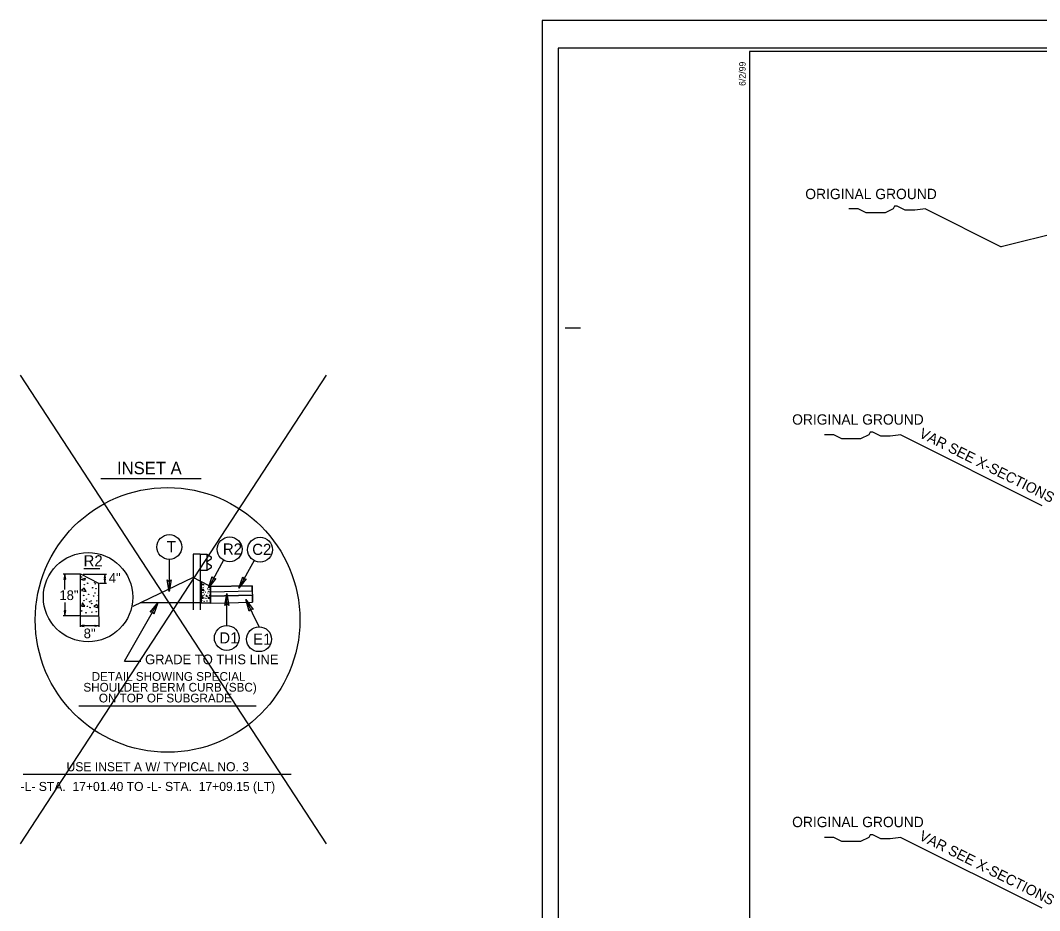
# Model space of a CAD drawing. Extents: x 573732 to 574187, y -53389 to -53257.
# Drawn here: x 573731.8 to 573830.3, y -53342.9 to -53256.9 of the extents above; entities that cross this region are included whole.
import ezdxf

# ---------------------------------------------------------------- set-up
doc = ezdxf.new("R2010")
doc.units = 0
for name, color, linetype in [('Old_Level_1', 7, 'Continuous'), ('Old_Level_11', 7, 'Continuous'), ('Prop Dimension', 7, 'Continuous'), ('Prop Shade Light', 7, 'Continuous'), ('Prop Shade Medium', 7, 'Continuous'), ('Prop Terminator CELL', 7, 'Continuous'), ('Sheet Cutting Line CELL', 7, 'Continuous'), ('Sheet Plot Border Inside CELL', 7, 'Continuous'), ('Sheet Plot Border Outside CELL', 7, 'Continuous'), ('Sheet Typical CELL', 7, 'Continuous'), ('Typical Curb CELL', 7, 'Continuous'), ('Typical Detail Wedge2 CELL', 7, 'Continuous'), ('Typical Guardrail CELL', 7, 'Continuous'), ('Typical ID Circle CELL', 7, 'Continuous'), ('Typical Pavement Slope CELL', 7, 'Continuous'), ('Typical Pavement Slope Information CELL', 7, 'Continuous'), ('Typical Shoulder Slope CELL', 7, 'Continuous'), ('Typical Slope Point Local CELL', 7, 'Continuous'), ('Typical Terminator CELL', 7, 'Continuous'), ('Typical Text General CELL', 7, 'Continuous'), ('Typical Text ID Circle CELL', 7, 'Continuous'), ('Typical Text Label CELL', 7, 'Continuous')]:
    doc.layers.add(name, color=color, linetype=linetype)

msp = doc.modelspace()

# ---------------------------------------------------------------- linework, layer by layer
at = {"layer": 'Old_Level_1'}
for p in [(573819.248, -53275.156), (573837.319, -53276.137)]:
    msp.add_line(p, (573826.579, -53278.822), dxfattribs=at)
at = {"layer": 'Old_Level_11'}
for points in [[(573736.234, -53310.921), (573736.142, -53310.411), (573736.055, -53310.926), (573736.146, -53310.86)], [(573740.076, -53310.794), (573740.007, -53310.411), (573739.942, -53310.797), (573740.009, -53310.747)], [(573739.945, -53310.906), (573740.007, -53311.29), (573740.079, -53310.906), (573740.011, -53310.954)], [(573736.06, -53313.949), (573736.142, -53314.461), (573736.239, -53313.948), (573736.147, -53314.013)], [(573738.008, -53315.337), (573737.625, -53315.403), (573738.01, -53315.471), (573737.961, -53315.403)], [(573739.042, -53315.337), (573739.425, -53315.403), (573739.04, -53315.471), (573739.089, -53315.403)]]:
    msp.add_lwpolyline(points, close=True, dxfattribs=at)
at = {"layer": 'Prop Dimension'}
for p, q in [((573731.844, -53336.476), (573761.397, -53291.214)), ((573761.397, -53336.476), (573731.844, -53291.214)), ((573737.618, -53310.411), (573735.986, -53310.411)), ((573736.142, -53311.894), (573736.142, -53310.411)), ((573737.918, -53310.411), (573740.16, -53310.411)), ((573740.007, -53310.411), (573740.007, -53311.29)), ((573740.16, -53311.311), (573739.488, -53311.311)), ((573736.142, -53313.169), (573736.142, -53314.461)), ((573741.884, -53318.814), (573745.12, -53313.202)), ((573737.562, -53314.461), (573735.986, -53314.461)), ((573737.625, -53314.524), (573737.625, -53315.523)), ((573739.425, -53314.524), (573739.425, -53315.523)), ((573739.425, -53315.403), (573737.625, -53315.403)), ((573741.884, -53318.814), (573743.463, -53318.814))]:
    msp.add_line(p, q, dxfattribs=at)
msp.add_circle((573738.381, -53312.646), 4.313, dxfattribs=at)
at = {"layer": 'Prop Shade Light'}
for p, q in [((573754.239, -53312.045), (573754.228, -53311.544)), ((573750.207, -53311.649), (573750.207, -53312.127)), ((573750.207, -53312.127), (573754.239, -53312.045))]:
    msp.add_line(p, q, dxfattribs=at)
msp.add_lwpolyline([(573754.228, -53311.544), (573750.207, -53311.627), (573750.197, -53311.628)], dxfattribs=at)
msp.add_ellipse((573750.196, -53311.649), major_axis=(0, 0.0209), ratio=0.5, start_param=4.712389, end_param=6.268072, dxfattribs=at)
at = {"layer": 'Prop Shade Medium'}
for p, q in [((573754.247, -53312.461), (573750.207, -53312.544)), ((573750.207, -53312.544), (573750.207, -53313.211)), ((573754.261, -53313.128), (573754.247, -53312.461)), ((573750.207, -53313.211), (573754.261, -53313.128))]:
    msp.add_line(p, q, dxfattribs=at)
at = {"layer": 'Prop Terminator CELL'}
for points in [[(573750.716, -53310.847), (573750, -53311.736), (573750.375, -53310.65), (573750.48, -53310.873)], [(573746.421, -53310.984), (573746.227, -53312.109), (573746.027, -53310.978), (573746.227, -53311.122)], [(573753.656, -53310.88), (573752.94, -53311.77), (573753.315, -53310.684), (573753.42, -53310.906)], [(573744.391, -53314.081), (573745.12, -53313.202), (573744.729, -53314.283), (573744.627, -53314.058)]]:
    msp.add_lwpolyline(points, close=True, dxfattribs=at)
at = {"layer": 'Sheet Cutting Line CELL'}
for p, q in [((573984.302, -53256.948), (573782.222, -53256.948)), ((573782.222, -53256.948), (573782.222, -53388.948))]:
    msp.add_line(p, q, dxfattribs=at)
at = {"layer": 'Sheet Plot Border Inside CELL'}
msp.add_lwpolyline([(573983.762, -53259.642), (573783.782, -53259.642), (573783.782, -53386.254), (573983.762, -53386.254)], close=True, dxfattribs=at)
at = {"layer": 'Sheet Plot Border Outside CELL'}
msp.add_lwpolyline([(573984.302, -53256.948), (573782.222, -53256.948), (573782.222, -53388.948), (573984.302, -53388.948)], close=True, dxfattribs=at)
at = {"layer": 'Sheet Typical CELL'}
msp.add_line((573784.442, -53286.648), (573785.942, -53286.648), dxfattribs=at)
msp.add_lwpolyline([(573982.262, -53259.948), (573802.262, -53259.948), (573802.262, -53385.948), (573982.262, -53385.948)], close=True, dxfattribs=at)
at = {"layer": 'Typical Curb CELL'}
for p, q in [((573737.625, -53310.468), (573737.682, -53310.411)), ((573737.625, -53310.468), (573737.625, -53314.461)), ((573739.425, -53311.311), (573737.682, -53310.411)), ((573737.673, -53310.926), (573738.09, -53310.805)), ((573738.045, -53311.049), (573737.673, -53310.926)), ((573738.09, -53310.805), (573738.045, -53311.049)), ((573739.425, -53314.461), (573739.425, -53311.311)), ((573750.207, -53311.627), (573749.194, -53311.105)), ((573749.307, -53311.206), (573749.335, -53311.177)), ((573749.307, -53311.206), (573749.307, -53313.202)), ((573749.331, -53311.435), (573749.539, -53311.374)), ((573749.517, -53311.496), (573749.331, -53311.435)), ((573749.539, -53311.374), (573749.517, -53311.496)), ((573750.207, -53313.202), (573750.207, -53311.627)), ((573738.014, -53311.786), (573737.735, -53311.989)), ((573737.735, -53311.989), (573738.182, -53312.095)), ((573738.182, -53312.095), (573738.014, -53311.786)), ((573749.501, -53311.865), (573749.362, -53311.966)), ((573749.362, -53311.966), (573749.586, -53312.02)), ((573749.416, -53312.572), (573749.37, -53312.726)), ((573749.532, -53312.734), (573749.416, -53312.572)), ((573749.586, -53312.02), (573749.501, -53311.865)), ((573737.844, -53313.201), (573737.751, -53313.508)), ((573737.751, -53313.508), (573738.074, -53313.525)), ((573738.074, -53313.525), (573737.844, -53313.201)), ((573739.213, -53313.353), (573738.935, -53313.556)), ((573738.935, -53313.556), (573739.382, -53313.663)), ((573739.382, -53313.663), (573739.213, -53313.353)), ((573749.307, -53313.202), (573750.207, -53313.202)), ((573749.37, -53312.726), (573749.532, -53312.734)), ((573750.101, -53312.648), (573749.962, -53312.75)), ((573749.962, -53312.75), (573750.185, -53312.803)), ((573750.185, -53312.803), (573750.101, -53312.648)), ((573737.625, -53314.461), (573739.425, -53314.461))]:
    msp.add_line(p, q, dxfattribs=at)
for centre, radius in [((573737.75, -53310.695), 0.0217), ((573738.012, -53311.433), 0.0217), ((573738.336, -53311.296), 0.0217), ((573739.029, -53311.219), 0.0217), ((573739.075, -53311.355), 0.0217), ((573749.369, -53311.319), 0.0108), ((573749.662, -53311.62), 0.0108), ((573750.009, -53311.581), 0.0108), ((573750.032, -53311.649), 0.0108), ((573737.966, -53312.48), 0.0217), ((573738.428, -53312.373), 0.0217), ((573738.813, -53311.741), 0.0217), ((573738.906, -53312.542), 0.0217), ((573739.06, -53312.234), 0.0217), ((573739.152, -53311.818), 0.0217), ((573739.369, -53312.465), 0.0217), ((573749.477, -53312.212), 0.0108), ((573749.486, -53312.464), 0.0108), ((573749.5, -53311.688), 0.0108), ((573749.617, -53312.391), 0.0108), ((573749.708, -53312.158), 0.0108), ((573749.763, -53312.518), 0.0108), ((573749.839, -53312.472), 0.0108), ((573749.862, -53312.602), 0.0108), ((573749.901, -53311.842), 0.0108), ((573749.947, -53312.243), 0.0108), ((573750.025, -53312.089), 0.0108), ((573750.071, -53311.881), 0.0108), ((573750.101, -53312.472), 0.0108), ((573750.179, -53312.204), 0.0108), ((573737.983, -53312.984), 0.0217), ((573738.244, -53312.839), 0.0217), ((573738.321, -53313.524), 0.0217), ((573738.537, -53313.092), 0.0217), ((573738.689, -53313), 0.0217), ((573738.735, -53313.261), 0.0217), ((573739.212, -53313), 0.0217), ((573749.37, -53312.957), 0.0108), ((573749.586, -53313.049), 0.0108), ((573749.655, -53312.734), 0.0108), ((573749.785, -53312.795), 0.0108), ((573749.87, -53313.019), 0.0108), ((573750.078, -53312.996), 0.0108), ((573737.751, -53313.97), 0.0217), ((573738.183, -53314.155), 0.0217), ((573738.581, -53313.647), 0.0217), ((573738.75, -53314.094), 0.0217), ((573739.166, -53314.047), 0.0217)]:
    msp.add_circle(centre, radius, dxfattribs=at)
at = {"layer": 'Typical Guardrail CELL'}
for p, q in [((573749.194, -53308.482), (573748.523, -53308.482)), ((573748.523, -53308.482), (573748.523, -53313.202)), ((573749.194, -53308.482), (573749.194, -53313.202)), ((573749.194, -53308.482), (573749.866, -53308.482)), ((573749.866, -53308.482), (573749.866, -53310.048)), ((573749.866, -53308.482), (573750.256, -53308.756)), ((573749.866, -53309.202), (573750.256, -53308.928)), ((573749.866, -53309.265), (573749.866, -53309.202)), ((573749.866, -53309.265), (573749.866, -53309.328)), ((573749.866, -53309.328), (573750.256, -53309.602)), ((573749.194, -53310.048), (573749.866, -53310.048)), ((573749.866, -53310.048), (573750.256, -53309.774)), ((573748.523, -53313.202), (573748.523, -53313.877)), ((573749.194, -53313.202), (573749.194, -53313.877))]:
    msp.add_line(p, q, dxfattribs=at)
for centre, start, end in [((573750.197, -53308.842), 304.9888, 54.99703), ((573750.197, -53309.688), 304.9634, 54.9941)]:
    msp.add_arc(centre, 0.105, start, end, dxfattribs=at)
at = {"layer": 'Typical ID Circle CELL'}
for p, q in [((573746.227, -53309.002), (573746.227, -53312.109)), ((573751.471, -53309.078), (573750, -53311.736)), ((573754.41, -53309.111), (573752.94, -53311.77)), ((573751.779, -53315.383), (573751.779, -53312.277)), ((573754.895, -53315.503), (573753.611, -53312.867))]:
    msp.add_line(p, q, dxfattribs=at)
for centre in [(573746.227, -53307.801), (573752.052, -53308.026), (573754.992, -53308.059), (573751.779, -53316.585), (573754.895, -53316.705)]:
    msp.add_circle(centre, 1.202, dxfattribs=at)
at = {"layer": 'Typical Pavement Slope CELL'}
for p, q in [((573748.523, -53310.758), (573742.69, -53313.541)), ((573749.194, -53311.105), (573748.523, -53310.758))]:
    msp.add_line(p, q, dxfattribs=at)
at = {"layer": 'Typical Pavement Slope Information CELL'}
msp.add_line((573749.307, -53313.202), (573743.399, -53313.202), dxfattribs=at)
at = {"layer": 'Typical Shoulder Slope CELL'}
for p, q in [((573750.207, -53311.627), (573754.228, -53311.545)), ((573750.207, -53311.627), (573750.207, -53313.211)), ((573754.228, -53311.544), (573754.261, -53313.128)), ((573750.207, -53312.127), (573754.239, -53312.045)), ((573750.207, -53312.544), (573754.247, -53312.461)), ((573750.207, -53313.211), (573754.265, -53313.128))]:
    msp.add_line(p, q, dxfattribs=at)
at = {"layer": 'Typical Slope Point Local CELL'}
for p, q in [((573816.884, -53296.978), (573830.501, -53303.786)), ((573816.884, -53335.847), (573830.501, -53342.655))]:
    msp.add_line(p, q, dxfattribs=at)
for points in [[(573819.248, -53275.156), (573818.211, -53275.285), (573817.951, -53275.285), (573817.562, -53275.285), (573817.303, -53275.285), (573817.043, -53275.156), (573816.784, -53275.026), (573816.525, -53274.896), (573816.265, -53274.896), (573816.135, -53275.156), (573815.876, -53275.285), (573815.616, -53275.415), (573815.357, -53275.545), (573815.098, -53275.545), (573814.838, -53275.545), (573814.579, -53275.545), (573814.32, -53275.545), (573814.06, -53275.545), (573813.801, -53275.545), (573813.542, -53275.545), (573813.282, -53275.415), (573813.023, -53275.285), (573812.764, -53275.156), (573812.374, -53275.156), (573812.115, -53275.156), (573811.856, -53275.156)], [(573816.884, -53296.978), (573815.847, -53297.107), (573815.587, -53297.107), (573815.198, -53297.107), (573814.938, -53297.107), (573814.679, -53296.978), (573814.42, -53296.848), (573814.16, -53296.718), (573813.901, -53296.718), (573813.771, -53296.978), (573813.512, -53297.107), (573813.252, -53297.237), (573812.993, -53297.367), (573812.734, -53297.367), (573812.474, -53297.367), (573812.215, -53297.367), (573811.956, -53297.367), (573811.696, -53297.367), (573811.437, -53297.367), (573811.178, -53297.367), (573810.918, -53297.237), (573810.659, -53297.107), (573810.4, -53296.978), (573810.01, -53296.978), (573809.751, -53296.978), (573809.491, -53296.978)], [(573816.884, -53335.847), (573815.847, -53335.976), (573815.587, -53335.976), (573815.198, -53335.976), (573814.938, -53335.976), (573814.679, -53335.847), (573814.42, -53335.717), (573814.16, -53335.586), (573813.901, -53335.586), (573813.771, -53335.847), (573813.512, -53335.976), (573813.252, -53336.106), (573812.993, -53336.235), (573812.734, -53336.235), (573812.474, -53336.235), (573812.215, -53336.235), (573811.956, -53336.235), (573811.696, -53336.235), (573811.437, -53336.235), (573811.178, -53336.235), (573810.918, -53336.106), (573810.659, -53335.976), (573810.4, -53335.847), (573810.01, -53335.847), (573809.751, -53335.847), (573809.491, -53335.847)]]:
    msp.add_lwpolyline(points, dxfattribs=at)
msp.add_circle((573746.056, -53314.842), 12.784, dxfattribs=at)
at = {"layer": 'Typical Terminator CELL'}
for points in [[(573751.577, -53313.448), (573751.779, -53312.277), (573751.987, -53313.455), (573751.779, -53313.305)], [(573753.943, -53314.009), (573753.611, -53312.867), (573754.314, -53313.836), (573754.062, -53313.792)]]:
    msp.add_lwpolyline(points, close=True, dxfattribs=at)
at = {"layer": 'Typical Text General CELL'}
msp.add_line((573737.5, -53323.149), (573754.619, -53323.149), dxfattribs=at)
at = {"layer": 'Typical Text ID Circle CELL'}
msp.add_line((573737.976, -53309.87), (573739.51, -53309.87), dxfattribs=at)
at = {"layer": 'Typical Text Label CELL'}
for p, q in [((573739.6, -53301.179), (573749.298, -53301.179)), ((573732.111, -53329.753), (573757.99, -53329.753))]:
    msp.add_line(p, q, dxfattribs=at)

# ---------------------------------------------------------------- texts
at = {"layer": 'Sheet Typical CELL'}
msp.add_text('6/2/99', height=0.63, rotation=90, dxfattribs=at).set_placement((573801.884, -53263.278))
at = {"layer": 'Typical Detail Wedge2 CELL'}
for s, p in [('4"', (573740.384, -53311.256)), ('18"', (573735.616, -53312.924)), ('8"', (573737.959, -53316.613))]:
    msp.add_text(s, height=0.9375, dxfattribs=at).set_placement(p)
at = {"layer": 'Typical Pavement Slope Information CELL'}
for p in [(573807.645, -53274.209), (573806.378, -53295.986), (573806.378, -53334.855)]:
    msp.add_text('ORIGINAL GROUND', height=1, rotation=360, dxfattribs=at).set_placement(p)
at = {"layer": 'Typical Slope Point Local CELL'}
for p in [(573818.555, -53297.154), (573818.555, -53336.022)]:
    msp.add_text('VAR SEE X-SECTIONS', height=1, rotation=333.43495, dxfattribs=at).set_placement(p)
at = {"layer": 'Typical Text General CELL'}
msp.add_text('GRADE TO THIS LINE', height=0.9375, dxfattribs=at).set_placement((573743.883, -53319.122))
at = {"layer": 'Typical Text ID Circle CELL'}
for s, p in [('T', (573745.983, -53308.308)), ('R2', (573751.406, -53308.534)), ('C2', (573754.235, -53308.567)), ('R2', (573737.949, -53309.673)), ('D1', (573751.062, -53317.117)), ('E1', (573754.324, -53317.237))]:
    msp.add_text(s, height=1.076, dxfattribs=at).set_placement(p)
at = {"layer": 'Typical Text Label CELL'}
msp.add_text('INSET A  ', height=1.2002, rotation=360, dxfattribs=at).set_placement((573741.178, -53300.776))
for s, height, p in [('DETAIL SHOWING SPECIAL', 0.84375, (573738.728, -53320.723)), ('SHOULDER BERM CURB (SBC)', 0.84375, (573737.931, -53321.767)), ('ON TOP OF SUBGRADE', 0.84375, (573739.421, -53322.811)), ('USE INSET A W/ TYPICAL NO. 3', 0.875, (573736.301, -53329.457)), ('-L- STA.  17+01.40 TO -L- STA.  17+09.15 (LT)', 0.875, (573731.867, -53331.362))]:
    msp.add_text(s, height=height, dxfattribs=at).set_placement(p)

doc.saveas('drawing.dxf')
